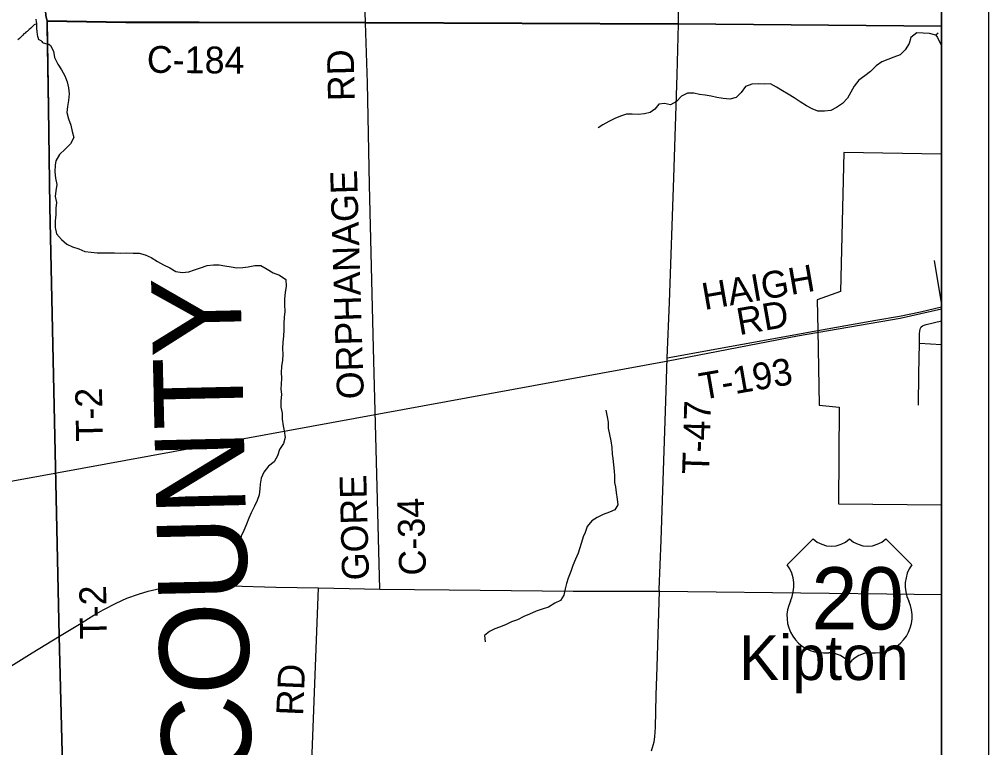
# Model space of a CAD drawing. Extents: x 0 to 34, y 0 to 22.
# Drawn here: x 6.946 to 9, y 18.319 to 19.863 of the extents above; entities that cross this region are included whole.
import ezdxf

# ---------------------------------------------------------------- set-up
doc = ezdxf.new("R2010")
doc.units = 0
for name, color, linetype in [('GM_X_City_Street', 7, 'Continuous'), ('GM_X_Corporation', 7, 'Continuous'), ('GM_X_County_Road', 7, 'Continuous'), ('GM_X_County_Road_Text', 7, 'Continuous'), ('GM_X_County_Text', 7, 'Continuous'), ('GM_X_Minor_Lake_Text', 7, 'Continuous'), ('GM_X_Minor_River', 7, 'Continuous'), ('GM_X_Rail_Line', 7, 'Continuous'), ('GM_X_Township_Road', 7, 'Continuous'), ('GM_X_Township_Road_Text', 7, 'Continuous'), ('GM_X_US_Location', 7, 'Continuous'), ('GM_X_US_Route', 7, 'Continuous'), ('GM_X_US_Shield', 7, 'Continuous'), ('SH_Data', 7, 'Continuous')]:
    doc.layers.add(name, color=color, linetype=linetype)

msp = doc.modelspace()

# ---------------------------------------------------------------- linework, layer by layer
at = {"layer": 'GM_X_City_Street'}
for p, q in [((8.9, 19.2619), (8.8856, 19.3519)), ((8.8534, 19.1764), (8.9, 19.1739))]:
    msp.add_line(p, q, dxfattribs=at)
for points in [[(8.6384, 19.2036), (8.7169, 19.2177), (8.7609, 19.2255), (8.8108, 19.2341), (8.8557, 19.2433), (8.9, 19.2539)], [(8.8514, 19.0455), (8.8521, 19.1107), (8.8534, 19.1764), (8.8536, 19.1849), (8.8538, 19.1958), (8.8542, 19.2031), (8.8554, 19.2081), (8.8571, 19.2111)], [(8.8571, 19.2111), (8.8599, 19.2135), (8.8637, 19.2151), (8.8677, 19.2161), (8.9, 19.2237)]]:
    msp.add_lwpolyline(points, dxfattribs=at)
at = {"layer": 'GM_X_Corporation'}
for points in [[(8.9, 14.1), (8.9, 20.9), (6.9799, 20.9), (6.9799, 20.8943), (6.9814, 20.8368), (6.9837, 20.7502), (6.9864, 20.657), (6.9927, 20.4427), (6.9931, 20.4255), (6.9989, 19.9212), (7.0018, 19.871), (7.0046, 19.8599), (7.0077, 19.6756), (7.0107, 19.4664), (7.0305, 18.5559), (7.0429, 18.0629), (7.0494, 17.8247), (7.0577, 17.449), (7.0649, 17.2134), (7.0651, 17.204), (7.0717, 16.9849), (7.0838, 16.6084), (7.1072, 15.3824)], [(7.1072, 15.3824), (7.0838, 16.6084), (7.0717, 16.9849), (7.0651, 17.204), (7.0649, 17.2134), (7.0577, 17.449), (7.0494, 17.8247), (7.0429, 18.0629), (7.0305, 18.5559), (7.0107, 19.4664), (7.0077, 19.6756), (7.0046, 19.8599), (7.0018, 19.871), (6.9989, 19.9212), (6.9931, 20.4255), (5.9453, 20.4158), (5.0033, 20.4116)], [(7.1072, 15.3824), (7.0838, 16.6084), (7.0717, 16.9849), (7.0651, 17.204), (7.0649, 17.2134), (7.0577, 17.449), (7.0494, 17.8247), (7.0429, 18.0629), (7.0305, 18.5559), (7.0107, 19.4664), (7.0077, 19.6756), (7.0046, 19.8599), (7.0018, 19.871), (6.9989, 19.9212), (6.9931, 20.4255), (5.9453, 20.4158), (5.0033, 20.4116)]]:
    msp.add_lwpolyline(points, dxfattribs=at)
for points in [[(8.9, 19.8484), (8.9, 20.9), (6.9799, 20.9), (6.9799, 20.8943), (6.9814, 20.8368), (6.9837, 20.7502), (6.9864, 20.657), (6.9927, 20.4427), (6.9931, 20.4255), (6.9989, 19.9212), (7.0018, 19.871), (7.0046, 19.8599), (7.1717, 19.8568), (7.3272, 19.8568), (7.6795, 19.8561), (8.3424, 19.8533)], [(8.9, 14.638), (8.9, 19.8484), (8.3424, 19.8533), (7.6795, 19.8561), (7.3272, 19.8568), (7.1717, 19.8568), (7.0046, 19.8599), (7.0077, 19.6756), (7.0107, 19.4664), (7.0305, 18.5559), (7.0429, 18.0629), (7.0494, 17.8247), (7.0577, 17.449), (7.0649, 17.2134), (7.0651, 17.204), (7.0717, 16.9849), (7.0838, 16.6084), (7.1072, 15.3824), (7.118, 14.8105), (7.1215, 14.6514), (7.384, 14.6494), (8.0793, 14.6442), (8.8452, 14.6384)], [(8.9, 18.8342), (8.9, 19.5773), (8.6935, 19.5806), (8.6862, 19.2858), (8.637, 19.2685), (8.6382, 19.2041), (8.6411, 19.0455), (8.683, 19.0408), (8.6818, 18.8364)]]:
    msp.add_lwpolyline(points, close=True, dxfattribs=at)
at = {"layer": 'GM_X_County_Road'}
msp.add_line((7.58, 18.6579), (7.7102, 18.6555), dxfattribs=at)
for points in [[(7.0048, 19.8594), (7.1719, 19.8563), (7.3274, 19.8563), (7.6797, 19.8556), (8.3426, 19.8527)], [(7.7102, 18.6555), (7.7019, 18.9526), (7.6967, 19.1658), (7.6878, 19.5122), (7.6835, 19.7287), (7.6797, 19.8556)], [(7.5268, 17.2021), (7.5356, 17.4654), (7.5568, 18.0484), (7.58, 18.6579)]]:
    msp.add_lwpolyline(points, dxfattribs=at)
at = {"layer": 'GM_X_Minor_River'}
for points in [[(6.9811, 19.8636), (6.9814, 19.8578), (6.9822, 19.8544), (6.9825, 19.8472), (6.9821, 19.8438), (6.9829, 19.8369), (6.984, 19.8305), (6.9847, 19.827), (6.9858, 19.8229), (6.9862, 19.821), (6.9889, 19.8194), (6.9915, 19.8179), (6.9934, 19.816)], [(6.9822, 19.8531), (6.9787, 19.8518), (6.9776, 19.851), (6.9749, 19.8488), (6.9726, 19.8465), (6.9703, 19.8446), (6.9665, 19.8412), (6.9646, 19.8393), (6.9623, 19.8374), (6.96, 19.8359), (6.9581, 19.834), (6.9558, 19.8321), (6.9531, 19.8295), (6.9501, 19.8261), (6.9463, 19.8227), (6.9428, 19.8196)], [(8.8932, 19.8338), (8.8879, 19.8292), (8.8749, 19.8329), (8.8612, 19.8335), (8.8479, 19.8344), (8.8355, 19.8244), (8.8314, 19.8115), (8.8232, 19.7984), (8.8127, 19.7877), (8.799, 19.783), (8.7861, 19.7782), (8.774, 19.7732), (8.762, 19.7647), (8.7495, 19.7527), (8.7379, 19.7435), (8.725, 19.7338), (8.7153, 19.7216), (8.7078, 19.7086), (8.7007, 19.6959), (8.6902, 19.6848), (8.6777, 19.6763), (8.6656, 19.6701), (8.652, 19.6684), (8.6383, 19.6686), (8.626, 19.6734), (8.6138, 19.6797), (8.6008, 19.6879), (8.5881, 19.6965), (8.5751, 19.7044), (8.5629, 19.7111), (8.5506, 19.7189), (8.5376, 19.7264), (8.5243, 19.7258), (8.5117, 19.7264), (8.498, 19.7259), (8.4848, 19.7204), (8.4754, 19.7078), (8.4652, 19.6974), (8.4516, 19.6938), (8.4375, 19.6952), (8.4242, 19.6973), (8.412, 19.6998), (8.399, 19.702), (8.3876, 19.7037), (8.375, 19.7066), (8.3621, 19.7065), (8.3492, 19.6999), (8.3383, 19.6887), (8.3258, 19.6817), (8.3132, 19.6846), (8.3015, 19.6833), (8.2928, 19.6726), (8.2826, 19.6656), (8.2709, 19.6625), (8.2576, 19.6616), (8.2446, 19.6622), (8.2329, 19.6617), (8.2196, 19.6577), (8.2078, 19.6526), (8.195, 19.6468), (8.1825, 19.6394), (8.1723, 19.6328)], [(8.8879, 19.8292), (8.8918, 19.8243), (8.8972, 19.8122), (8.9, 19.8078)], [(6.9934, 19.816), (6.9949, 19.8137), (6.9968, 19.8133), (6.9991, 19.8125), (7.0014, 19.8118), (7.0086, 19.8102)], [(7.0086, 19.8102), (7.0121, 19.8075), (7.0187, 19.7955), (7.0203, 19.7818), (7.0273, 19.7682), (7.0351, 19.7557), (7.0425, 19.7429), (7.0475, 19.7308), (7.05, 19.7175), (7.0513, 19.705), (7.0499, 19.6913), (7.0481, 19.6784), (7.0464, 19.6658), (7.05, 19.6518), (7.0551, 19.6389), (7.0582, 19.6253), (7.0618, 19.6124), (7.0544, 19.5994), (7.0431, 19.5879), (7.031, 19.5763), (7.0236, 19.5633), (7.0218, 19.5538), (7.0212, 19.5401), (7.0229, 19.5265), (7.0253, 19.5132), (7.0235, 19.4995), (7.0222, 19.4873), (7.0246, 19.4748), (7.0236, 19.4626), (7.023, 19.4489), (7.0216, 19.4356), (7.0221, 19.4216), (7.0246, 19.4087), (7.035, 19.3962), (7.0469, 19.3865), (7.0587, 19.3809), (7.0721, 19.3769), (7.0851, 19.3706), (7.098, 19.3692), (7.111, 19.3682), (7.1205, 19.368), (7.1475, 19.3683), (7.1604, 19.3677), (7.1734, 19.3682), (7.1871, 19.3672), (7.2, 19.3674), (7.2126, 19.3641), (7.2256, 19.3582), (7.239, 19.35), (7.2513, 19.3429), (7.2646, 19.3366), (7.2777, 19.3284), (7.291, 19.3262), (7.3051, 19.3279), (7.3172, 19.3322), (7.3301, 19.3366), (7.3437, 19.3409), (7.3574, 19.3426), (7.3696, 19.3423), (7.3818, 19.3402), (7.3947, 19.3385), (7.4069, 19.3363), (7.4198, 19.3368), (7.4312, 19.3385), (7.4449, 19.3409), (7.4578, 19.3415), (7.4712, 19.3333), (7.4842, 19.3258), (7.4976, 19.321), (7.5107, 19.3113), (7.5112, 19.2976), (7.5091, 19.2839), (7.5077, 19.2706), (7.5082, 19.2577), (7.5084, 19.244), (7.507, 19.2318), (7.5064, 19.2185), (7.5062, 19.2048), (7.5056, 19.1915), (7.5046, 19.1786), (7.5036, 19.1653), (7.5045, 19.1528), (7.5035, 19.1406), (7.5017, 19.1273), (7.5011, 19.1143), (7.5012, 19.1022), (7.501, 19.0896), (7.5003, 19.0797), (7.5012, 19.0676), (7.4999, 19.0547), (7.5004, 19.041), (7.5032, 19.0281), (7.503, 19.0152), (7.505, 19.0015), (7.5074, 18.9905), (7.5091, 18.9769), (7.5058, 18.9639), (7.4972, 18.9513), (7.4932, 18.9379), (7.4861, 18.9249), (7.4741, 18.916)], [(8.189, 19.0349), (8.1914, 19.0208), (8.1935, 19.0091), (8.194, 18.9962), (8.1964, 18.9829), (8.1996, 18.9696), (8.2013, 18.9556), (8.2026, 18.9415), (8.2035, 18.9321), (8.2051, 18.9184), (8.2068, 18.9051), (8.2073, 18.8952), (8.2075, 18.8816), (8.2091, 18.8721), (8.2107, 18.8599), (8.2128, 18.8463), (8.2141, 18.8341), (8.2081, 18.823), (8.1964, 18.8183), (8.1835, 18.8133), (8.1706, 18.8074), (8.1589, 18.7997), (8.1496, 18.7882), (8.1447, 18.7756), (8.1411, 18.766), (8.1374, 18.7538), (8.1333, 18.7409), (8.1304, 18.7313), (8.1245, 18.7187), (8.1189, 18.7053), (8.1145, 18.6924), (8.1093, 18.6786), (8.1057, 18.6672), (8.1027, 18.6558), (8.0995, 18.6424), (8.0931, 18.6313), (8.081, 18.6255), (8.067, 18.6173), (8.0542, 18.613), (8.0409, 18.6087), (8.0269, 18.6024), (8.0152, 18.5974), (8.0015, 18.5904), (7.989, 18.586), (7.9762, 18.5794), (7.9637, 18.5747), (7.9538, 18.5712), (7.9421, 18.5657), (7.9315, 18.5569), (7.9332, 18.5436)], [(7.4741, 18.916), (7.4639, 18.9034), (7.4584, 18.8904), (7.4566, 18.8774), (7.4556, 18.8679), (7.4542, 18.8554), (7.4498, 18.8432), (7.4442, 18.8309), (7.4371, 18.8172), (7.4323, 18.8057), (7.4275, 18.7927), (7.422, 18.7798), (7.4164, 18.7672), (7.4135, 18.7534)]]:
    msp.add_lwpolyline(points, dxfattribs=at)
at = {"layer": 'GM_X_Rail_Line'}
for points in [[(7.0292, 18.9027), (7.7081, 19.027), (8.3212, 19.1393), (8.5947, 19.1923), (8.8129, 19.2299), (8.9, 19.2492)], [(2.1, 18.4805), (2.8461, 18.4459), (3.8274, 18.4086), (4.0038, 18.4053), (4.1245, 18.4086), (4.3015, 18.4114), (4.5799, 18.4555), (5.3876, 18.5934), (5.9987, 18.7127), (6.6286, 18.8295), (7.0292, 18.9027)]]:
    msp.add_lwpolyline(points, dxfattribs=at)
at = {"layer": 'GM_X_Township_Road'}
for p, q in [((7.0308, 18.5554), (7.0168, 19.1971)), ((8.3185, 19.1457), (8.6384, 19.2036))]:
    msp.add_line(p, q, dxfattribs=at)
for points in [[(8.3426, 19.8527), (8.3432, 19.91), (8.3441, 19.9593), (8.3443, 19.9836), (8.3443, 20.002), (8.3436, 20.0142), (8.3428, 20.0221), (8.3417, 20.0292), (8.3372, 20.0564), (8.3372, 20.0637), (8.3397, 20.0845), (8.3454, 20.1413), (8.3474, 20.1785), (8.3505, 20.3601), (8.3545, 20.636)], [(7.6797, 19.8556), (7.6745, 20.0219)], [(7.0048, 19.8594), (7.002, 19.8704), (6.9991, 19.9206)], [(7.005, 19.8494), (7.0049, 19.8514), (7.0048, 19.8594)], [(7.0168, 19.1971), (7.0109, 19.4659), (7.0079, 19.675), (7.005, 19.8494)], [(8.3029, 18.6506), (8.302, 18.6544), (8.306, 18.7591), (8.3159, 19.0537), (8.3185, 19.1457), (8.3235, 19.2629), (8.3327, 19.5271), (8.3398, 19.7457), (8.3426, 19.8527)], [(8.2857, 18.3126), (8.2894, 18.3242), (8.2916, 18.3313), (8.293, 18.3422), (8.2942, 18.362), (8.2958, 18.4308), (8.2977, 18.4906), (8.3029, 18.6506)]]:
    msp.add_lwpolyline(points, dxfattribs=at)
at = {"layer": 'GM_X_US_Route'}
for p, q in [((7.58, 18.6579), (7.7102, 18.6555)), ((8.7842, 18.6452), (8.9, 18.6439))]:
    msp.add_line(p, q, dxfattribs=at)
for points in [[(7.0308, 18.5554), (7.0738, 18.5809), (7.1041, 18.6), (7.1239, 18.6114), (7.1511, 18.6258), (7.1735, 18.6359), (7.1986, 18.6449), (7.2187, 18.6508), (7.2371, 18.6553), (7.2633, 18.6596), (7.2848, 18.6624), (7.3066, 18.6638), (7.3314, 18.6638), (7.3943, 18.6626), (7.4897, 18.6596), (7.58, 18.6579)], [(7.7102, 18.6555), (7.857, 18.654), (8.1195, 18.6513), (8.3029, 18.6506), (8.6619, 18.6466), (8.7842, 18.6452)], [(4.5081, 18.3834), (4.529, 18.3836), (4.6996, 18.3849), (5.1455, 18.3911), (5.4829, 18.394), (6, 18.4001), (6.2576, 18.4014), (6.4701, 18.4022), (6.6805, 18.4035), (6.7388, 18.4084), (6.7834, 18.4183), (6.8306, 18.4357), (6.874, 18.4589), (6.9732, 18.5205), (7.0308, 18.5554)]]:
    msp.add_lwpolyline(points, dxfattribs=at)
at = {"layer": 'GM_X_US_Shield'}
for p, q in [((8.6283, 18.762), (8.5734, 18.7071)), ((8.8371, 18.7071), (8.7822, 18.762)), ((8.6503, 18.5203), (8.6613, 18.5203)), ((8.7492, 18.5203), (8.7602, 18.5203))]:
    msp.add_line(p, q, dxfattribs=at)
for centre, radius, start, end in [((8.6668, 18.8012), 0.0549, 225.573, 314.427), ((8.7437, 18.8012), 0.0549, 225.573, 314.427), ((8.5104, 18.663), 0.0769, 334.5471, 35.0009), ((8.9001, 18.663), 0.0769, 144.9991, 205.4529), ((8.6495, 18.5972), 0.0769, 154.8319, 270.6383), ((8.761, 18.5972), 0.0769, 269.3617, 25.1681), ((8.6613, 18.4654), 0.0549, 36.8699, 90), ((8.7492, 18.4654), 0.0549, 90, 143.1301)]:
    msp.add_arc(centre, radius, start, end, dxfattribs=at)
at = {"layer": 'SH_Data'}
for p, q in [((9, 21), (9, 14)), ((8.9, 20.9), (8.9, 14.1))]:
    msp.add_line(p, q, dxfattribs=at)

# ---------------------------------------------------------------- texts
at = {"layer": 'GM_X_County_Road_Text'}
for s, rotation, p in [('C-184', 359.4494, (7.216, 19.7498)), ('RD', 91.4806, (7.6571, 19.6904)), ('ORPHANAGE', 91.7493, (7.6762, 19.0586)), ('GORE', 91.5142, (7.6871, 18.6746)), ('C-34', 91.7153, (7.8081, 18.6848)), ('RD', 87.5314, (7.5471, 18.3861))]:
    msp.add_text(s, height=0.05682, rotation=rotation, dxfattribs=at).set_placement(p)
at = {"layer": 'GM_X_County_Text'}
msp.add_text('LORAIN COUNTY', height=0.189394, rotation=91.3059, dxfattribs=at).set_placement((7.4618, 17.2371))
at = {"layer": 'GM_X_Minor_Lake_Text'}
msp.add_text('Kipton', height=0.09475, rotation=359.9958, dxfattribs=at).set_placement((8.4714, 18.4627))
at = {"layer": 'GM_X_Township_Road_Text'}
for s, rotation, p in [('HAIGH', 9.8844, (8.3978, 19.2467)), ('RD', 9.9507, (8.4715, 19.1935)), ('T-193', 9.8778, (8.3922, 19.0563)), ('T-2', 91.1215, (7.1232, 18.9687)), ('T-47', 88.2318, (8.4072, 18.8979)), ('T-2', 90.9543, (7.1316, 18.5496))]:
    msp.add_text(s, height=0.05682, rotation=rotation, dxfattribs=at).set_placement(p)
at = {"layer": 'GM_X_US_Location'}
for s in ['0', '/']:
    msp.add_text(s, height=0.000189, dxfattribs=at).set_placement((8.7052, 18.6346))
msp.add_text('20', height=0.000189, rotation=0, dxfattribs=at).set_placement((8.6661, 18.5954))
at = {"layer": 'GM_X_US_Shield'}
msp.add_text('20', height=0.13184, dxfattribs=at).set_placement((8.6243, 18.5698))

doc.saveas('drawing.dxf')
